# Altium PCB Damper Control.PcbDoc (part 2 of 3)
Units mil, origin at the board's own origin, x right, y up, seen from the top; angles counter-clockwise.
Board outline 4586.61 x 2962.6 mil, 4 copper layers (Top Layer, GND Plane, Power Plane, Bottom Layer), stack 70.356 mil thick; 195 components, 143 nets, 589 pads, 854 vias.
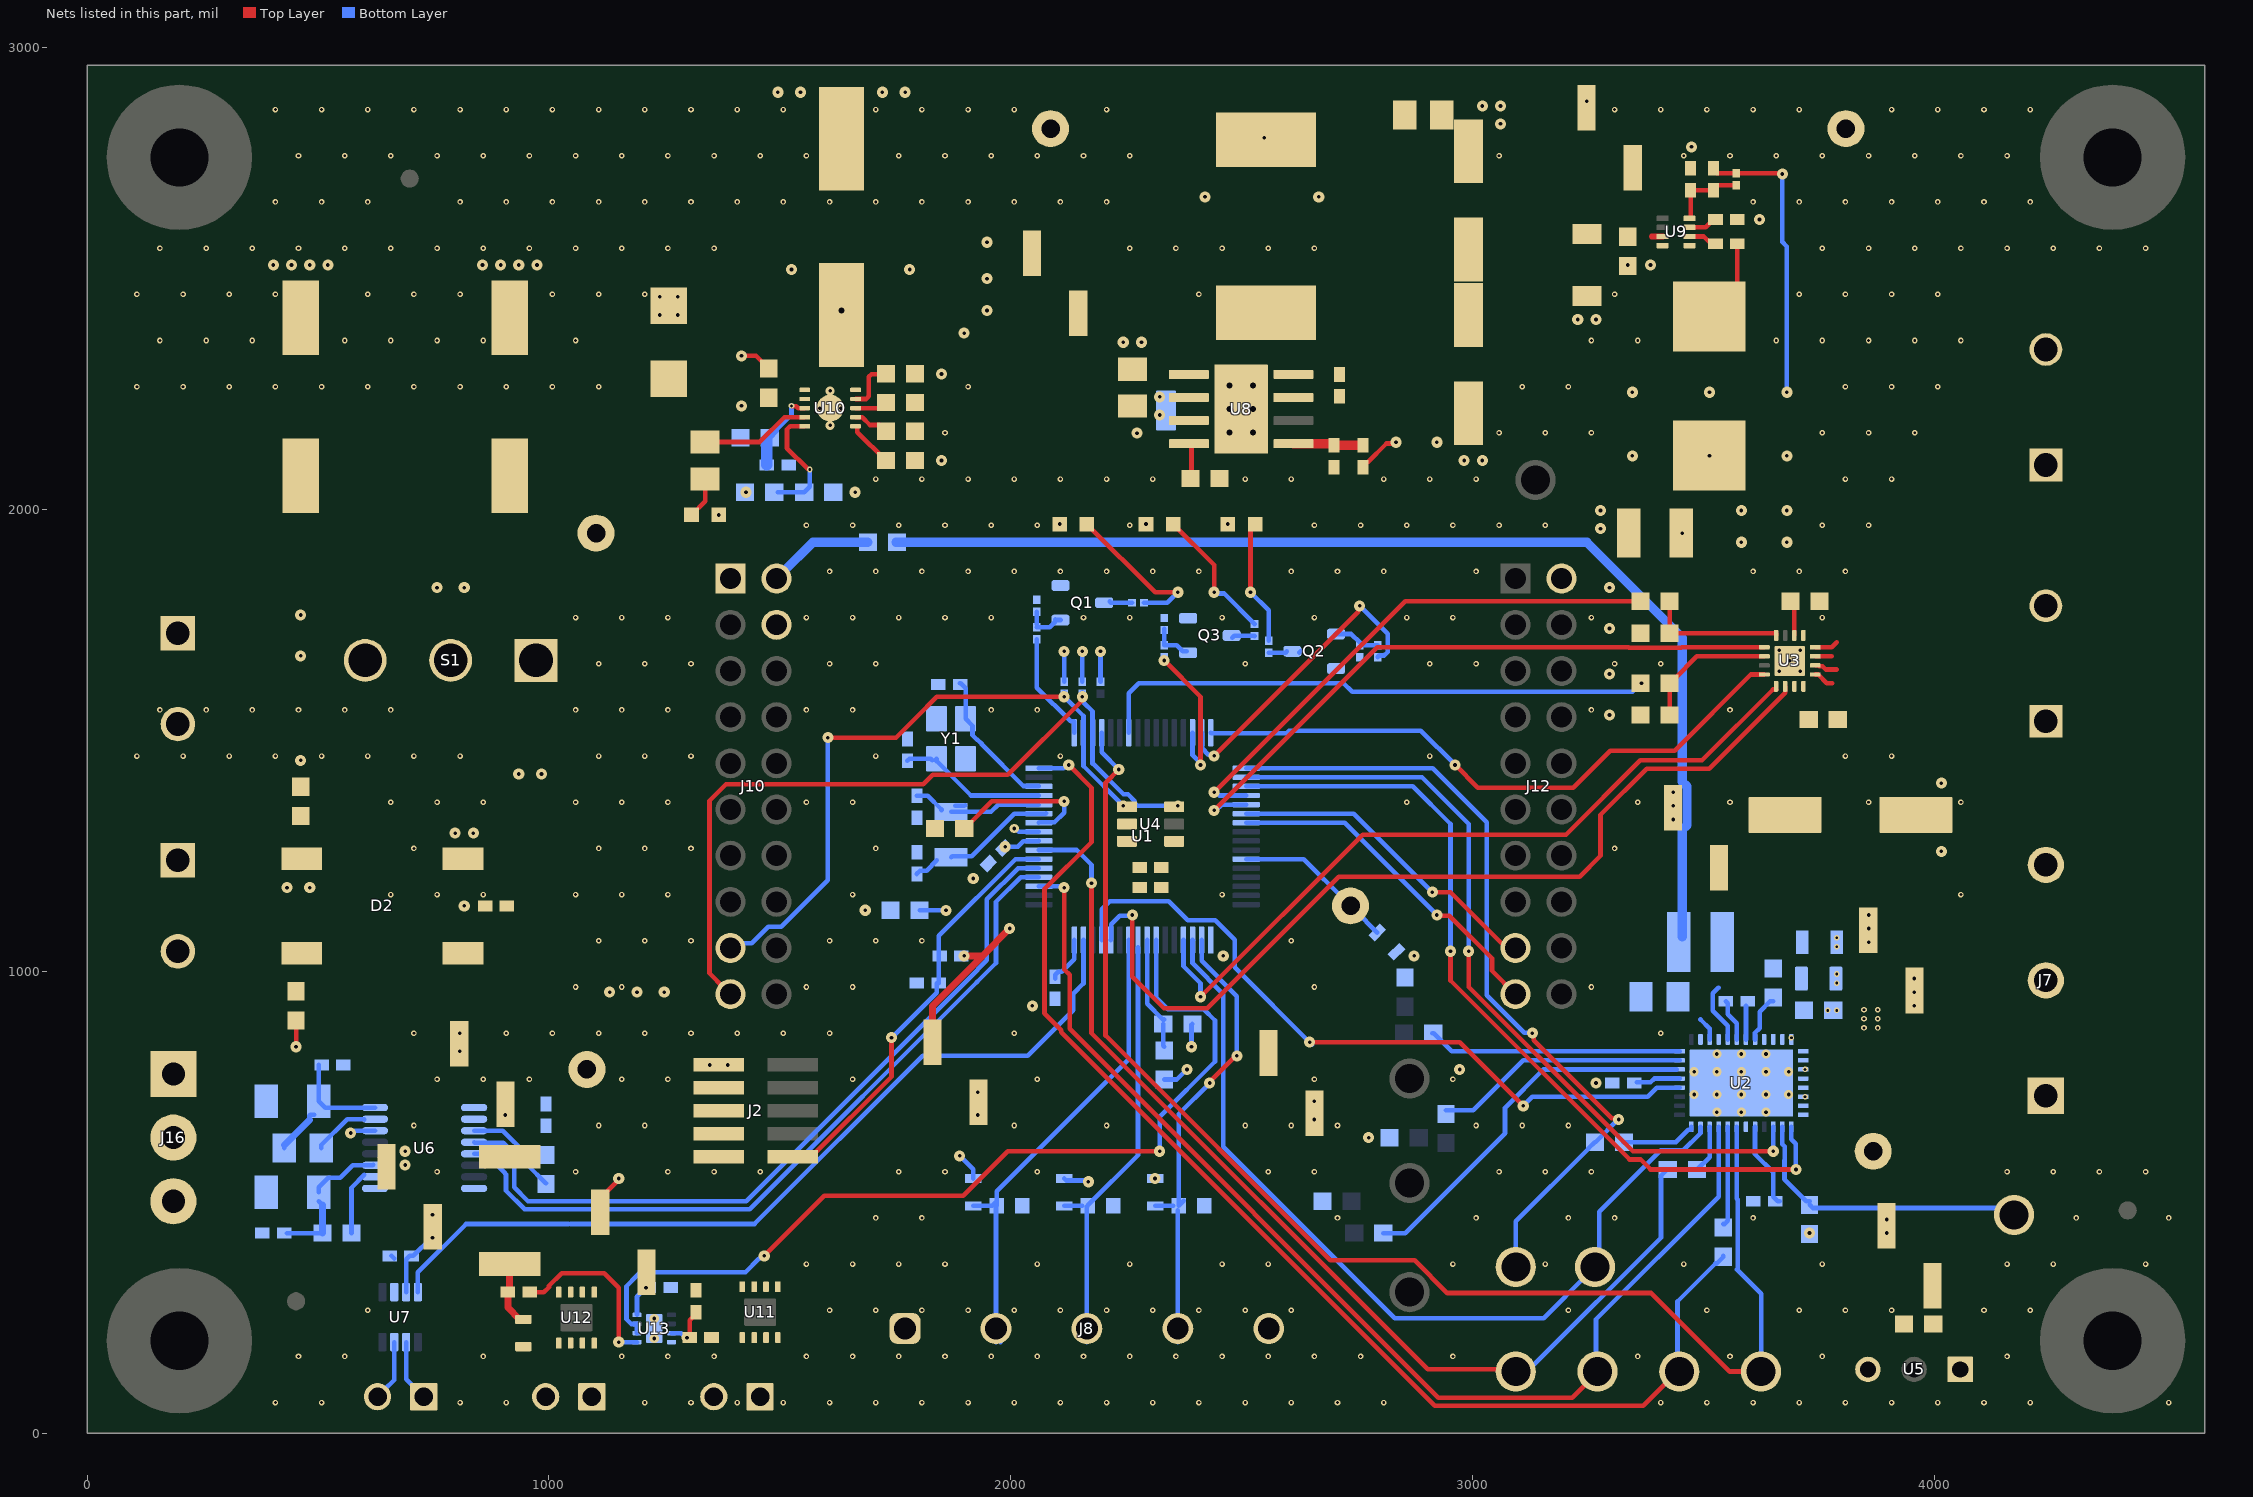
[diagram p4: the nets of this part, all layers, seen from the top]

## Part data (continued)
J7: library part CMP-0055483-1, "Terminal Block, 3x1, 6.35 mm, TH", Manufacturer="Phoenix Contact", Supplier Part Number 1=277-1270-ND
J8: library part CMP-0055532-1, "Terminal Block, 5mm, 5x1, R/A, TH", Color=Green, Current_A=16A, Manufacturer="Phoenix Contact", Supplier Part Number 1=277-2521-ND, Voltage_V=400V
J10 J12: library part CMP-0075442-1, "Connector, Receptacle, 100mil, 10x2, Gold plated, TH", Manufacturer=Samtec
J15 J21 J22: library part CMP-0002337-1, "Header, 100mil, 2x1, Tin, TH", Color=Black, Current_A=3A, Manufacturer="Sullins Connector Solutions", Supplier Part Number 1=S1012E-02-ND, Voltage_V=1.8kV
J16: library part CMP-0074916-1, "Terminal Block, 3.5mm Pitch, 3x1, TH", Color=Grey, Current_A=6A, Manufacturer="On-Shore Technology", Supplier Part Number 1=ED1515-ND, Voltage_V=150V
J18 J19: library part CMP-0055486-1, "TERM BLOCK 2POS 5mm, TH", Manufacturer="Phoenix Contact", Supplier Part Number 1=651-1729018
L1: library part CMP-0059315-2, "Inductor, Drum Core, Ferrite, 47 uH, 0.2 A, 1.5 ohm, SMD", Manufacturer="NIC Components", Value1="1.5 ohm", Value2=0.2A, ValueDisplayed=47uH
L2: library part CMP-0061458-2, "Inductor, Shielded, Ferrite, 68 uH, 4.3 A, 0.074 ohm, SMD", Manufacturer=Coilcraft, Supplier Part Number 1=994-MSS1210-683MEB, Value1="0.074 ohm", Value2=4.3A, ValueDisplayed=68uH
L3: library part CMP-0098677-1, "WE-HCI SMT Flat Wire High Current Inductor, size 1050, 7.8uH, 10.7A, 13.6mOhm", Case/Size Code=1050, DC Resistance=13.6mOhm, Inductance=7.8uH, Manufacturer="Wurth Elektronik", Operating Temperature Max=150°C, Operating Temperature Min=-40°C, Performance Rated Current=10.7A, Saturation Current=9.5A, Self Resonant Frequency=23MHz
Logo1: library part CMP-0074838-1, "Texas Instrument Corporate Signature"
Logo2: library part CMP-0074844-1
Logo3: library part CMP-0074847-1, "FCC_disclaimer"
Logo4: library part CMP-0074769-3, Manufacturer="Texas Instruments"
Q1 Q2 Q3: library part CMP-0000461-2, "Transistor, NPN, 40 V, 0.6 A, SOT-23", Manufacturer="ON Semiconductor", Supplier Part Number 1=MMBT2222ALT1GOSCT-ND, Value1="0.6 A"
R1: library part CMP-0027294-2, "RES, 100, 1%, 0.05 W, 0201", Manufacturer="Yageo America", Power_W=50mW, Supplier Part Number 1=311-100MCT-ND, TempCo="200 ppm/C", Tolerance_%=1%, Value2=0.05W, Value_Code=100R, ValueDisplayed=100
R2 R41 R44: library part CMP-0028069-1, "RES, 100 k, 1%, 0.05 W, 0201", Manufacturer="Yageo America", Power_W=50mW, Supplier Part Number 1=603-RC0201FS-7D100KL, TempCo="200 ppm/C", Tolerance_%=1%, Value2=0.05W, Value_Code=100k
R3 R42 R45: library part CMP-0027131-1, "RES, 4.7 k, 5%, 0.05 W, 0201", Manufacturer="Yageo America", Power_W=50mW, Supplier Part Number 1=311-4.7KNCT-ND, TempCo="200 ppm/C", Tolerance_%=5%, Value2=0.05W, Value_Code=4k70, ValueDisplayed=4.7k
R4: library part CMP-0023630-3, "RES, 100 k, 0.1%, 0.1 W, 0603", Manufacturer="Yageo America", Power_W=100mW, Supplier Part Number 1=603-RT0603BRD07100KL, TempCo="25 ppm/C", Tolerance_%=0.1%, Value2=0.1W, Value_Code=100k
R5: library part CMP-0026935-3, "RES, 47 k, 5%, 0.063 W, AEC-Q200 Grade 0, 0402", Manufacturer=Vishay-Dale, Power_W=63mW, Supplier Part Number 1=541-47KJCT-ND, TempCo="200 ppm/C", Tolerance_%=5%, Value2=0.063W, Value_Code=47k0, ValueDisplayed=47k
R6 R7 R8 R9 R10 R11 R12 R23 R47: library part CMP-0025697-4, "RES, 0, 5%, 0.1 W, AEC-Q200 Grade 0, 0603", Manufacturer=Vishay-Dale, Power_W=100mW, Supplier Part Number 1=541-0.0GCT-ND, TempCo="200 ppm/C", Tolerance_%=5%, Value2=0.1W, Value_Code=0000, ValueDisplayed=0
R13: library part CMP-0025830-4, "RES, 5.1 k, 5%, 0.1 W, AEC-Q200 Grade 0, 0603", Manufacturer=Vishay-Dale, Power_W=100mW, Supplier Part Number 1=541-5.1KGCT-ND, TempCo="200 ppm/C", Tolerance_%=5%, Value2=0.1W, Value_Code=5k10, ValueDisplayed=5.1k
R14 R15 R16: library part CMP-0025729-4, "RES, 1.0 k, 5%, 0.1 W, AEC-Q200 Grade 0, 0603", Manufacturer=Vishay-Dale, Power_W=100mW, Supplier Part Number 1=541-1.0KGCT-ND, TempCo="200 ppm/C", Tolerance_%=5%, Value2=0.1W, Value_Code=1k00, ValueDisplayed=1.0k
R17 R18 R19 R53: library part CMP-0025686-1, "RES, 10.0 k, 0.1%, 0.1 W, AEC-Q200 Grade 1, 0603", Manufacturer=Vishay-Dale, Power_W=100mW, Supplier Part Number 1=TNP10.0KAACT-ND, TempCo="25 ppm/C", Tolerance_%=0.1%, Value2=0.1W, Value_Code=10k0, ValueDisplayed=10.0k
R20 R21 R22: library part CMP-0027242-1, "RES, 4.7 k, 5%, 0.05 W, 0201", Manufacturer="Yageo America", Power_W=50mW, Supplier Part Number 1=603-RC0201JR-7D4K7L, TempCo="200 ppm/C", Tolerance_%=5%, Value2=0.05W, Value_Code=4k70, ValueDisplayed=4.7k
R24: library part CMP-0019016-2, "RES, 562, 0.1%, 0.125 W, 0805", Manufacturer="Susumu Co Ltd", Power_W=125mW, Supplier Part Number 1=RG20P562BCT-ND, TempCo="25 ppm/C", Tolerance_%=0.1%, Value2=0.125W, Value_Code=562R, ValueDisplayed=562
R25: library part CMP-0024912-2, "RES, 200, 0.5%, 0.1 W, 0603", Manufacturer="Yageo America", Power_W=100mW, TempCo="50 ppm/C", Tolerance_%=0.5%, Value2=0.1W, Value_Code=200R, ValueDisplayed=200
R26 R27: library part CMP-0018797-2, "RES, 1.00 k, 0.1%, 0.25 W, 1206", Manufacturer="TE Connectivity", Power_W=250mW, Supplier Part Number 1=A105676-ND, TempCo="15 ppm/C", Tolerance_%=0.1%, Value2=0.25W, Value_Code=1k00, ValueDisplayed=1.00k
R28: library part CMP-0022544-4, "RES, 64.9 k, 1%, 0.1 W, AEC-Q200 Grade 0, 0603", Manufacturer=Vishay-Dale, Power_W=100mW, Supplier Part Number 1=541-64.9KHCT-ND, TempCo="100 ppm/C", Tolerance_%=1%, Value2=0.1W, Value_Code=64k9, ValueDisplayed=64.9k
R29: library part CMP-0025950-3, "RES, 100 k, 1%, 0.063 W, AEC-Q200 Grade 0, 0402", Manufacturer=Vishay-Dale, Power_W=63mW, Supplier Part Number 1=541-100KLCT-ND, TempCo="100 ppm/C", Tolerance_%=1%, Value2=0.063W, Value_Code=100k
R30: library part CMP-0026553-2, "RES, 7.15 k, 1%, 0.063 W, AEC-Q200 Grade 0, 0402", Manufacturer=Vishay-Dale, Power_W=63mW, Supplier Part Number 1=541-7.15KLCT-ND, TempCo="100 ppm/C", Tolerance_%=1%, Value2=0.063W, Value_Code=7k15, ValueDisplayed=7.15k
R31: library part CMP-0022731-2, "RES, 1.00 M, 1%, 0.125 W, 0603", Manufacturer=Vishay/Beyschlag, Power_W=125mW, Supplier Part Number 1=MCT0603-1.00M-CFCT-ND, TempCo="50 ppm/C", Tolerance_%=1%, Value2=0.125W, Value_Code=1M00, ValueDisplayed=1.00M
R32: library part CMP-0026323-2, "RES, 38.3 k, 1%, 0.063 W, AEC-Q200 Grade 0, 0402", Manufacturer=Vishay-Dale, Power_W=63mW, Supplier Part Number 1=541-38.3KLCT-ND, TempCo="100 ppm/C", Tolerance_%=1%, Value2=0.063W, Value_Code=38k3, ValueDisplayed=38.3k
R33: library part CMP-0025698-4, "RES, 100 k, 5%, 0.1 W, AEC-Q200 Grade 0, 0603", Manufacturer=Vishay-Dale, Power_W=100mW, Supplier Part Number 1=541-100KGCT-ND, TempCo="200 ppm/C", Tolerance_%=5%, Value2=0.1W, Value_Code=100k
R34: library part CMP-0022030-4, "RES, 12.1 k, 1%, 0.1 W, AEC-Q200 Grade 0, 0603", Manufacturer=Vishay-Dale, Power_W=100mW, Supplier Part Number 1=541-12.1KHCT-ND, TempCo="100 ppm/C", Tolerance_%=1%, Value2=0.1W, Value_Code=12k1, ValueDisplayed=12.1k
R35: library part CMP-0020887-3, "RES, 13.7 k, 1%, 0.125 W, AEC-Q200 Grade 0, 0805", Manufacturer=Vishay-Dale, Power_W=125mW, Supplier Part Number 1=541-13.7KCCT-ND, TempCo="100 ppm/C", Tolerance_%=1%, Value2=0.125W, Value_Code=13k7, ValueDisplayed=13.7k
R36: library part CMP-0022659-4, "RES, 95.3 k, 1%, 0.1 W, AEC-Q200 Grade 0, 0603", Manufacturer=Vishay-Dale, Power_W=100mW, Supplier Part Number 1=541-95.3KHCT-ND, TempCo="100 ppm/C", Tolerance_%=1%, Value2=0.1W, Value_Code=95k3, ValueDisplayed=95.3k
R37: library part CMP-0025862-4, "RES, 8.2 k, 5%, 0.1 W, AEC-Q200 Grade 0, 0603", Manufacturer=Vishay-Dale, Power_W=100mW, Supplier Part Number 1=541-8.2KGCT-ND, TempCo="200 ppm/C", Tolerance_%=5%, Value2=0.1W, Value_Code=8k20, ValueDisplayed=8.2k
R38: library part CMP-0026285-2, "RES, 30.9 k, 1%, 0.063 W, AEC-Q200 Grade 0, 0402", Manufacturer=Vishay-Dale, Power_W=63mW, Supplier Part Number 1=541-30.9KLCT-ND, TempCo="100 ppm/C", Tolerance_%=1%, Value2=0.063W, Value_Code=30k9, ValueDisplayed=30.9k
R39 R50: library part CMP-0025958-3, "RES, 10.0 k, 1%, 0.063 W, AEC-Q200 Grade 0, 0402", Manufacturer=Vishay-Dale, Power_W=63mW, Supplier Part Number 1=541-10.0KLCT-ND, TempCo="100 ppm/C", Tolerance_%=1%, Value2=0.063W, Value_Code=10k0, ValueDisplayed=10.0k
R40 R43: library part CMP-0027526-1, "RES, 261, 1%, 0.05 W, 0201", Manufacturer="Yageo America", Power_W=50mW, Supplier Part Number 1=YAG2541CT-ND, TempCo="200 ppm/C", Tolerance_%=1%, Value2=0.05W, Value_Code=261R, ValueDisplayed=261
R46: library part CMP-0025885-5, "RES, 0, 5%, 0.1 W, 0603", Manufacturer=Yageo, Power_W=100mW, Supplier Part Number 1=311-0.0GRCT-ND, TempCo="200 ppm/C", Tolerance_%=5%, Value2=0.1W, Value_Code=0000, ValueDisplayed=0
R48: library part CMP-0026025-3, "RES, 158 k, 1%, 0.063 W, AEC-Q200 Grade 0, 0402", Manufacturer=Vishay-Dale, Power_W=63mW, Supplier Part Number 1=541-158KLCT-ND, TempCo="100 ppm/C", Tolerance_%=1%, Value2=0.063W, Value_Code=158k
R49: library part CMP-0026403-2, "RES, 49.9 k, 1%, 0.063 W, AEC-Q200 Grade 0, 0402", Manufacturer=Vishay-Dale, Power_W=63mW, Supplier Part Number 1=541-49.9KLCT-ND, TempCo="100 ppm/C", Tolerance_%=1%, Value2=0.063W, Value_Code=49k9, ValueDisplayed=49.9k
R51: library part CMP-0015444-3, "RES, 120, 1%, 1 W, AEC-Q200 Grade 0, 2512", Manufacturer=Vishay-Dale, Power_W=1W, Supplier Part Number 1=541-120AFCT-ND, TempCo="100 ppm/C", Tolerance_%=1%, Value_Code=120R, ValueDisplayed=120
R52: library part CMP-0037671-1, "12 kOhms ±0.1% 0.1W, 1/10W Chip Resistor 0603 (1608 Metric) Anti-Sulfur, Automotive AEC-Q200, Moisture Resistant Thin Film", Digikey Part Number=541-9817-1-ND, Manufacturer=Vishay, Mouser Part Number=71-TNPW060312K0BYEN, Operating Temperature Range="-55°C to +155°C", Power_W=100mW, TempCo=10ppm/°C, Tolerance_%=0.1%
S1: library part CMP-0002255-1, "Switch, Slide, SPDT, On-Off-On, 1 Pos, 6A, 120 VAC, 28 VDC, TH", CurrentRating_mA=6kA, Manufacturer="C&K Components", Supplier Part Number 1=CKN5051-ND
TP1 TP2 TP3 TP4 TP5 TP6 TP8: library part CMP-0055155-2, "Test Point, Compact, Blue, TH", Color=Blue, Manufacturer="Keystone Electronics", PartNumber=5122, Supplier Part Number 1=36-5122-ND
TP7 TP13 TP14 TP15: library part CMP-0055155-2, "Test Point, Compact, Blue, TH", Color=Blue, Manufacturer="Keystone Electronics", Supplier Part Number 1=36-5122-ND
TP9 TP10 TP16 TP19: library part CMP-0055138-2, "Test Point, Miniature, Black, TH", Color=Black, Manufacturer="Keystone Electronics", PartNumber=5001, Supplier Part Number 1=36-5001-ND
TP11: library part CMP-0055154-1, "Test Point, Miniature, Blue, TH", Color=Blue, Manufacturer=Keystone, Supplier Part Number 1=36-5117-ND
TP20: library part CMP-0055137-2, "Test Point, Miniature, Red, TH", Color=Red, Manufacturer="Keystone Electronics", PartNumber=5000, Supplier Part Number 1=36-5000-ND
U1: library part CMP-0093960-1, "Mixed-Signal Microcontrollers With CAN-FD Interface LQFP64", Frequency_Fixed=80MHz, Manufacturer="Texas Instruments", Max Supply Voltage=3.6V, Min Supply Voltage=1.62V, Operating Temperature Range="-40°C to +125°C"
U2: library part CMP-0096344-1, "Three-Phase Integrated FET Motor Driver", Manufacturer="Texas Instruments", Max Supply Voltage=35V, Min Supply Voltage=4.5V, Nominal Supply Current=1.5-19000uA, Operating Temperature Range="-40°C to +150°C", Switching Frequency=400kHz
U3: library part CMP-0861028-1, "Stepper Drivers With Integrated Current Sense, 1/256 Microstepping, STEP/DIR Interface and smart tune Technology, RTE0016J (WQFN-16)", Alternate Manufacturer="Texas Instruments"
U4: library part CMP-0090454-1, "3-Axis Linear Hall Effect Sensor With I2C Interface", Manufacturer="Texas Instruments", Max Supply Voltage=5.5V, Min Supply Voltage=2.3V, Operating Supply Current=2.8mA, Operating Temperature Range="-40°C to +150°C"
U5: library part CMP-0074653-4, "Precision Analog Output Temperature Sensor, LP0003A (TO-92-3)", Alternate Manufacturer="Texas Instruments", Operating Temperature Range="-40 to 150 C", Rating=Catalog
U6: library part CMP-0013034-2, "ISO1212DBQR, DBQ00016A, DBQ0016A (SSOP-16)", Alternate Manufacturer="Texas Instruments", Alternate PartNumber=ISO1212DBQ
U7: library part CMP-0080984-2, "3.3-V CAN Transceivers with CAN FD (Flexible Data Rate), DCN0008A (SOT-23-8)", Alternate Manufacturer="Texas Instruments", Alternate PartNumber=TCAN334GDCNT
U8: library part CMP-0094072-1, "SIMPLE SWITCHER 4.2-V to 80-V, 2-A Synchronous Buck Converter", Manufacturer="Texas Instruments", Max Supply Voltage=80V, Min Supply Voltage=4.2V, Nominal Supply Current=40uA, Operating Temperature Range="-40°C to +150°C", Output Voltage=1-75V, Switching Frequency=200-1100kHz
U9: library part CMP-0094457-2, "3.8-V to 30-V, 2-A Synchronous Buck Converter in SOT583 Package", Manufacturer="Texas Instruments", Max Supply Voltage=30V, Min Supply Voltage=3.8V, Nominal Supply Current=12uA, Operating Temperature Range="-40°C to +150°C", Output Voltage=0.8-22V, Switching Frequency=310-2100kHz
U10: library part CMP-0093898-1, Manufacturer="Texas Instruments", Operating Temperature Range=to
U11 U12: library part CMP-0083941-3, "14 V Bidirectional Flat-Clamp Surge Protection Device, DRB0008A (VSON-8)", Alternate Manufacturer="Texas Instruments", Alternate PartNumber=TVS1401DRBR, Operating Temperature Range="-40 to 125 C"
U13: library part CMP-0860798-1, "2-Channel, 1MHz, RRIO, 1.8V to 5.5V Operational Amplifier for Cost-Optimized Systems, DSG0008A (WSON-8)", Alternate Manufacturer="Texas Instruments", Alternate PartNumber=TLV9002IDSGT, Operating Temperature Range="-40 to 125 C", Rating=Catalog
Y1: library part CMP-0098168-2, "Crystal 40MHz ±10ppm (Tol) ±20ppm (Stability) 12pF FUND 40Ohm 4-Pin Mini-CSMD T/R", Frequency Stability=20ppm, Frequency Tolerance=10ppm, Frequency_Fixed=40MHz, Load Capacitance=12pF, Manufacturer="Seiko Epson", Operating Temperature Range="-40°C to +105°C"
Y2: library part CMP-0004693-3, "Crystal, 32.768 KHz, 12.5 pF, SMD", Frequency_Fixed=32.768kHz, Manufacturer=Epson
ZZ1: library part CMP-0003616-3
ZZ2: library part CMP-0077236-1
ZZ3: library part CMP-0077237-1
ZZ4: library part CMP-0077238-1

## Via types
v1: diameter 12, hole 6, Top Layer to Bottom Layer, tented both sides, 463 vias
v2: diameter 24, hole 8, Top Layer to Bottom Layer, tented both sides, 202 vias
v3: diameter 12, hole 6, Top Layer to Bottom Layer, 145 vias
v4: diameter 19.68, hole 7.87, Top Layer to Bottom Layer, 19 vias
v5: diameter 19.68, hole 7.87, Top Layer to Bottom Layer, tented both sides, 16 vias
v6: diameter 24.8, hole 12.99, Top Layer to Bottom Layer, 7 vias
v7: diameter 20, hole 8, Top Layer to Bottom Layer, tented both sides, 1 vias
v8: diameter 24, hole 8, Top Layer to Bottom Layer, 1 vias

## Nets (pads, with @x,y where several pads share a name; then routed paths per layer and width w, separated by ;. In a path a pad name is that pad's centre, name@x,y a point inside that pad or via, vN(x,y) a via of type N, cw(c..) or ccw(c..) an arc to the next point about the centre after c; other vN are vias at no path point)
0_10VDC: J15.1 R48.2 U11.1 U11.2 U11.3 U11.4
3V3: C49.1 C51.1 D1.1 D5.1 D6.1 J1.1 J2.1 J8.5 J9.1 J10.1 J11.1 J13.1 J14.1 J23.1 L3.2 R13.1 R17.2 R18.2 R19.2 R20.2 R21.2 R22.2 R38.2 R46.1 | length 1094.2
  Top Layer w10: J23.1@1111.42,478.54 1111.42,508.27 1151.57,548.43 v2(1151.57,551.18) ; R38.2@3523.15,2739.11 R38.2@3522.68,2738.64 3522.68,2734.82 3529.49,2728.01 C49.1@3571.21,2728.01 ; C49.1@3571.9,2728.01 v2@3673.02,2728.01
  Bottom Layer w10: v2(1889.76,600.39) 1919.29,570.87 R19.2@1919.29,551.18 ; R18.2@2116.14,551.18 2120.41,546.92 2161.94,546.92 2165.35,543.5 v2@2165.35,541.34 ; R20.2@2116.14,1627.17 v2(2116.14,1692.91) ; R21.2@2155.51,1627.17 v2(2155.51,1692.91) ; R22.2@2194.88,1627.17 v2(2194.88,1692.91) ; R46.1@2332.68,765.75 2360.24,765.75 v2(2381.89,787.4) ; v2(3671.26,2726.38) 3671.26,2579.43 3681.1,2569.59 v2(3681.1,2253.94)
  other v2: 3730.32,433.07 3897.64,433.07 3897.64,462.6 2168.41,544.24 2312.99,551.18 688.98,580.71 688.98,610.24 2657.48,679.13 1929.13,688.98 2657.48,718.5 1929.13,738.19 1348.43,797.24 1387.8,797.24 807.09,826.77 807.09,866.14 3582.68,1929.13 3681.1,1929.13 3454.72,1948.82 2106.3,1968.5 2293.31,1968.5 2470.47,1968.5 3582.68,1998.03 3681.1,1998.03 3346.46,2116.14 3513.78,2116.14 3681.1,2116.14 3513.78,2253.94
  other v8: 3346.46,2253.94
4_20mA: J22.1 R52.1 U12.1 U12.2 U12.3 U12.4
5V: C19.2 L1.2 R47.2 U2.3 | length 2495.9
  Bottom Layer w10: 3494.09,895.67 3513.78,875.98 U2.3@3513.78,852.36
  Bottom Layer w20: R47.2@1751.97,1929.13 R47.2@1753.94,1929.13 3248.03,1929.13 3454.72,1722.44 3454.72,1410.36 3464.91,1400.17 3464.91,1316.37 3454.72,1306.18 L1.2@3454.72,1074.8
15VDC: C39.1 C40.1 C41.1 J3.1 J4.1 J20.1 L2.2 R29.2 | length 96.4
  Top Layer w10: R29.2@2762.87,2091.72 2762.87,2095.66 2769.68,2102.47 2773.62,2102.47 2814.14,2142.99 2831.97,2142.99 v2(2834.65,2145.67)
  other v2: 3956.69,925.2 3956.69,954.72 3956.69,984.25 3435.04,1328.74 3435.04,1358.27 3435.04,1387.8 2923.23,2145.67 2421.26,2677.17 2667.32,2677.17 2549.21,2805.12 3248.03,2883.86
24VDC_IN: J19.1 S1.3
  other v2: 462.6,1683.07 462.6,1771.65
AOUT1: J6.1 U3.1 | length 44.8
  Top Layer w10: U3.1@3742.51,1642.71 3749.05,1642.71 3767.74,1624.02 3779.53,1624.02
AOUT2: J6.2 U3.2 | length 50.5
  Top Layer w10: U3.2@3742.51,1662.4 3749.05,1662.4 3750.86,1660.58 3758.22,1660.58 3765.26,1653.54 3789.37,1653.54
AVDD: C15.1 U2.25 | length 185.7
  Bottom Layer w10: U2.25@3612.2,663.39 3612.2,603.88 3651.57,564.51 3651.57,511.81 3661.42,501.97 C15.1@3665.35,501.97
BOUT1: J5.2 U3.4 | length 51.3
  Top Layer w10: U3.4@3742.51,1701.77 3778.54,1701.77 3789.37,1712.6
BOUT2: J5.1 U3.3 | length 36
  Top Layer w10: U3.3@3742.51,1682.08 3778.54,1682.08
C_Ctrl: U1.23 U13.6 U13.7 | length 2004.4
  Top Layer w10: v2(1466.54,383.86) 1596.3,513.62 1897.17,513.62 1993.78,610.24 v2@2327.98,610.24
  Bottom Layer w10: U13.6@1190.94,216.54 U13.7@1190.94,236.22 1178.81,236.22 1168.23,246.8 1168.23,317.84 1190.94,340.56 1198.5,348.11 1426.03,348.11 1455.07,377.14 1456.03,377.14 1462.75,383.86 v2(1466.54,383.86) ; U1.23@2315.36,1067.71 2315.36,942.51 2340.47,917.4 2418.72,917.4 2442.76,893.36 2442.76,804.7 2322.83,684.78 v2(2322.83,610.24)
CANH: J21.2 U7.7 | length 117.4
  Bottom Layer w10: J21.2@639.76,98.43 643.43,94.76 645.16,94.76 665.35,114.96 U7.7@665.35,196.85
CANL: J21.1 U7.6 | length 159
  Bottom Layer w10: U7.6@690.94,196.85 690.94,116.93 709.45,98.43 J21.1@728.35,98.43 ; J21.1@729.13,68.9 J21.1@753.19,92.95
DECAY_TOFF: U1.5 U3.9 | length 1413.1
  Top Layer w10: v2(2440.95,1348.43) 2794.29,1701.77 3338.1,1701.77 3339.16,1700.71 3452.18,1700.71 3453.24,1701.77 U3.9@3632.28,1701.77
  Bottom Layer w10: v2(2440.95,1348.43) 2444.73,1348.43 2457.33,1361.02 U1.5@2510.25,1361.02
DIR: U1.64 U3.12 | length 1353.9
  Top Layer w10: v2(2962.6,1446.85) 3011.81,1397.64 3218.5,1397.64 3298.74,1477.87 3438.06,1477.87 3602.9,1642.71 U3.12@3632.28,1642.71
  Bottom Layer w10: U1.64@2433.47,1516.53 2434.26,1515.75 2597.7,1515.75 2602.89,1520.94 2888.51,1520.94 v2(2962.6,1446.85)
DRV_OFF: U1.3 U2.21 | length 1829.2
  Top Layer w10: v2(2952.76,1043.31) 2952.76,980.06 3340.45,592.36 3364.33,592.36 3385.83,570.87 v2(3700.79,570.87)
  Bottom Layer w10: U1.3@2510.25,1400.39 2871.26,1400.39 2952.76,1318.9 v2(2952.76,1043.31) ; U2.21@3690.94,663.39 3690.94,636.44 3700.79,626.6 v2(3700.79,570.87)
EFuse_IN: C37.1 C38.1 C42.1 D3.1 D4.1 R31.2 R33.1 S1.2 TP20.1 U10.1 U10.2
  other v2: 757.87,1830.71 816.93,1830.71 1368.11,1988.19 1427.17,2037.4 1417.32,2224.41
EFuse_OUT: C50.1 J17.1 U10.10
  other v2: 1899.61,2381.89 1948.82,2431.1 1948.82,2500 1525.59,2519.69 1781.5,2519.69 1948.82,2578.74
  other v6: 1633.86,2431.1
EN_FAULT: U1.20 U3.13 | length 1660
  Top Layer w10: v2(2411.42,944.88) 2762.28,1295.75 3202.8,1295.75 3363.75,1456.69 3497.44,1456.69 3651.06,1610.31 U3.13@3657.59,1610.31
  Bottom Layer w10: U1.20@2374.42,1067.71 2374.42,1011.41 2411.42,974.41 v2(2411.42,944.88)
F_GND: C52.2 C55.2 J16.3 U6.9 U6.14 | length 54.9
  Bottom Layer w10: v2(570.87,649.61) 574.65,649.61 579.83,654.79 U6.14@623.65,654.79
F_IN1: J16.1 R26.2
F_IN2: J16.2 R27.2
GND: C1.2 C2.2 C3.2 C4.2 C5.2 C6.2 C7.2 C8.2 C9.2 C10.1 C11.2 C13.2 C15.2 C18.2 C19.1 C20.2 C21.2 C22.2 C23.2 C24.2 C25.2 C26.2 C27.2 C28.2 C29.2 C30.2 C31.1 C32.2 C33.2 C34.2 C35.2 C37.2 C38.2 C39.2 C40.2 C41.2 C42.2 C43.2 C44.2 C45.2 C47.1 C48.1 C50.2 C51.2 C54.1 D2.2 D3.2 J2.3 J2.5 J2.7 J2.9 J8.1 J10.4 J12.2 J15.2 J19.2 J22.2 Q1.2 Q2.2 Q3.2 R2.1 R4.2 R7.1 R12.1 R28.1 R30.1 R32.1 R34.1 R36.2 R37.2 R39.1 R41.1 R44.1 R49.1 R51.1 R53.2 TP9.1 TP16.1 TP19.1 U1.17 U1.41 U2.2 U2.4 U2.26 U2.41 U3.5 U3.16 U3.17 U4.2 U4.3 U5.3 U6.1 U6.8 U7.2 U8.1 U8.9 U9.4 U10.11 U11.5 U11.6 U11.7 U11.8 U12.5 U12.6 U12.7 U12.8 U13.4 U13.9@1228.35,226.38 Y1.2 Y1.4 | length 243
  Top Layer w10: v2(452.76,836.61) C33.2@452.76,893.7 ; v2(1417.32,2332.68) 1448.82,2332.68 1461.69,2319.8 1462.68,2319.8 1476.38,2306.1 C42.2@1476.38,2305.12
  Bottom Layer w10: C30.2@659.45,383.86 C30.2@665.35,377.95 ; v7(2007.87,1309.06) 2010.58,1309.06 2017.67,1301.97 U1.41@2061.43,1301.97 ; v2(2391.73,836.61) 2391.73,883.86 C9.2@2393.7,885.83
  other v1: 408,66 508,66 808,66 908,66 1208,66 1308,66 1408,66 1508,66 1608,66 1708,66 1808,66 1908,66 2008,66 2108,66 2208,66 2308,66 2408,66 2508,66 2608,66 2708,66 2808,66 3408,66 3508,66 3608,66 3708,66 3808,66 3908,66 4008,66 4108,66 4208,66 4508,66 458,166 558,166 858,166 1158,166 1258,166 1358,166 1558,166 1658,166 1758,166 1858,166 1958,166 2058,166 2158,166 2258,166 2358,166 2458,166 2558,166 2658,166 2758,166 2958,166 3358,166 3558,166 3758,166 4158,166 608,266 1608,266 1708,266 1808,266 1908,266 2008,266 2108,266 2208,266 2308,266 2408,266 2508,266 2608,266 3208,266 3508,266 3708,266 3808,266 3908,266 4108,266 4208,266 1558,366 1658,366 1758,366 1858,366 2058,366 2258,366 2458,366 2558,366 2958,366 3158,366 3458,366 3758,366 4158,366 4258,366 4458,366 1708,466 1808,466 2708,466 3008,466 3208,466 3308,466 3608,466 4308,466 4508,466 758,566 1058,566 1258,566 1358,566 1458,566 1758,566 1858,566 2058,566 2558,566 2658,566 3058,566 3158,566 3258,566 4158,566 4258,566 4358,566 4458,566 708,666 1108,666 1208,666 2008,666 2208,666 2508,666 2608,666 2708,666 3008,666 3108,666 3208,666 758,766 858,766 958,766 1158,766 1258,766 1658,766 2058,766 2658,766 2958,766 708,866 908,866 1008,866 1108,866 1208,866 1308,866 1408,866 1508,866 1608,866 2008,866 3408,866 1058,966 1158,966 1558,966 1658,966 2658,966 3258,966 1108,1066 1208,1066 1308,1066 1608,1066 1708,1066 1808,1066 2608,1066 658,1166 758,1166 858,1166 1058,1166 1158,1166 1258,1166 1658,1166 2458,1166 4058,1166 708,1266 1108,1266 1208,1266 1308,1266 1708,1266 3308,1266 658,1366 758,1366 858,1366 1058,1366 1158,1366 1258,1366 1558,1366 1658,1366 2858,1366 3358,1366 3558,1366 3858,1366 4058,1366 108,1466 208,1466 308,1466 408,1466 508,1466 608,1466 708,1466 808,1466 1108,1466 1208,1466 1308,1466 1708,1466 2108,1466 2908,1466 3808,1466 3908,1466 158,1566 258,1566 358,1566 458,1566 558,1566 658,1566 1058,1566 1158,1566 1258,1566 1558,1566 1658,1566 1958,1566 2058,1566 3258,1566 3558,1566 1108,1666 1208,1666 1308,1666 1608,1666 1708,1666 2508,1666 2908,1666 3008,1666 3308,1666 3408,1666 1058,1766 1158,1766 1258,1766 1558,1766 1658,1766 1758,1766 1858,1766 1958,1766 2158,1766 2258,1766 2458,1766 2658,1766 2858,1766 2958,1766 3258,1766 3758,1766 1608,1866 1708,1866 1808,1866 1908,1866 2008,1866 2108,1866 2208,1866 2308,1866 2408,1866 2608,1866 2708,1866 2808,1866 3008,1866 3608,1866 3708,1866 3808,1866 1558,1966 1658,1966 1758,1966 1858,1966 1958,1966 2058,1966 2258,1966 2658,1966 2758,1966 2858,1966 2958,1966 3058,1966 3158,1966 3758,1966 3858,1966 1708,2066 1808,2066 1908,2066 2008,2066 2108,2066 2208,2066 2308,2066 2508,2066 2608,2066 2808,2066 2908,2066 3008,2066 3808,2066 3908,2066 1858,2166 3058,2166 3158,2166 3258,2166 3758,2166 3858,2166 3958,2166 108,2266 208,2266 308,2266 408,2266 508,2266 608,2266 708,2266 808,2266 908,2266 1008,2266 1108,2266 1908,2266 3108,2266 3208,2266 3808,2266 3908,2266 4008,2266 158,2366 258,2366 358,2366 558,2366 658,2366 758,2366 858,2366 1058,2366 3258,2366 3358,2366 3658,2366 3758,2366 3858,2366 3958,2366 4058,2366 108,2466 208,2466 308,2466 408,2466 608,2466 708,2466 808,2466 1008,2466 1108,2466 1208,2466 2408,2466 3308,2466 3708,2466 3808,2466 3908,2466 4008,2466 158,2566 258,2566 358,2566 458,2566 558,2566 658,2566 758,2566 858,2566 958,2566 1058,2566 1158,2566 1258,2566 1358,2566 2258,2566 2358,2566 2458,2566 2558,2566 2658,2566 3758,2566 3858,2566 3958,2566 4058,2566 4158,2566 4258,2566 4358,2566 4458,2566 408,2666 508,2666 608,2666 808,2666 908,2666 1008,2666 1108,2666 1208,2666 1308,2666 1408,2666 1508,2666 1608,2666 1708,2666 1808,2666 1908,2666 2008,2666 2108,2666 2208,2666 3608,2666 3708,2666 3808,2666 3908,2666 4008,2666 4108,2666 4208,2666 458,2766 558,2766 658,2766 758,2766 858,2766 958,2766 1058,2766 1158,2766 1258,2766 1358,2766 1458,2766 1558,2766 1758,2766 1858,2766 1958,2766 2058,2766 2158,2766 2258,2766 3058,2766 3458,2766 3558,2766 3658,2766 3758,2766 3858,2766 3958,2766 4058,2766 4158,2766 408,2866 508,2866 608,2866 708,2866 808,2866 908,2866 1008,2866 1108,2866 1208,2866 1308,2866 1408,2866 1508,2866 1708,2866 1808,2866 1908,2866 2008,2866 2208,2866 3308,2866 3408,2866 3508,2866 3608,2866 3708,2866 3908,2866 4008,2866 4108,2866 4208,2866
  other v2: 2775.59,639.76 3267.72,757.87 2972.44,787.4 2047.24,925.2 1131.89,954.72 1190.94,954.72 1250,954.72 2460.63,1033.46 2874.02,1033.46 1685.3,1132.18 816.93,1141.73 1919.29,1200.79 4015.75,1259.84 797.24,1299.21 836.61,1299.21 4015.75,1407.48 462.6,1456.69 3297.24,1555.12 3297.24,1643.7 3297.24,1742.13 3297.24,1830.71 3277.56,1958.66 3277.56,1998.03 1663.39,2037.4 1850.39,2106.3 2982.28,2106.3 3021.65,2106.3 1850.39,2293.31 2244.09,2362.2 2283.46,2362.2 3228.35,2411.42 3267.72,2411.42 1240.16,2421.26 1279.53,2421.26 1240.16,2460.63 1279.53,2460.63 403.54,2529.53 442.91,2529.53 482.28,2529.53 521.65,2529.53 856.3,2529.53 895.67,2529.53 935.04,2529.53 974.41,2529.53 3336.61,2529.53 3385.83,2529.53 3622.05,2627.95 3474.41,2785.43 3060.96,2835.06 3021.65,2874.02 3061.02,2874.02 1496.06,2903.54 1545.28,2903.54 1722.44,2903.54 1771.65,2903.54
  other v3: 1058,966 1158,966 1108,1066 1208,1066 1308,1066 658,1166 758,1166 858,1166 1058,1166 1158,1166 1258,1166 708,1266 1108,1266 1208,1266 1308,1266 658,1366 758,1366 858,1366 1058,1366 1158,1366 1258,1366 108,1466 208,1466 308,1466 408,1466 508,1466 608,1466 708,1466 808,1466 1108,1466 1208,1466 1308,1466 158,1566 258,1566 358,1566 458,1566 558,1566 658,1566 1058,1566 1158,1566 1258,1566 1108,1666 1208,1666 1308,1666 1058,1766 1158,1766 1258,1766 108,2266 208,2266 308,2266 408,2266 508,2266 608,2266 708,2266 808,2266 908,2266 1008,2266 1108,2266 158,2366 258,2366 358,2366 558,2366 658,2366 758,2366 858,2366 1058,2366 108,2466 208,2466 308,2466 408,2466 608,2466 708,2466 808,2466 1008,2466 1108,2466 1208,2466 158,2566 258,2566 358,2566 458,2566 558,2566 658,2566 758,2566 858,2566 958,2566 1058,2566 1158,2566 1258,2566 1358,2566 2258,2566 408,2666 508,2666 608,2666 808,2666 908,2666 1008,2666 1108,2666 1208,2666 1308,2666 1408,2666 1508,2666 1608,2666 1708,2666 1808,2666 1908,2666 2008,2666 2108,2666 2208,2666 458,2766 558,2766 658,2766 758,2766 858,2766 958,2766 1058,2766 1158,2766 1258,2766 1358,2766 1458,2766 1558,2766 1758,2766 1858,2766 1958,2766 2058,2766 2158,2766 2258,2766 408,2866 508,2866 608,2866 708,2866 808,2866 908,2866 1008,2866 1108,2866 1208,2866 1308,2866 1408,2866 1508,2866 1708,2866 1808,2866 1908,2866 2008,2866 2208,2866
  other v4: 1228.35,204.72 1228.35,248.03 3664.56,1649.4 3710.23,1649.4 3687.39,1672.24 3664.56,1695.07 3710.23,1695.07 1609.33,2182.21 1586.7,2219.62 1631.97,2219.62 1609.33,2257.02
  other v5: 3529.53,694.88 3582.68,694.88 3635.83,694.88 3480.31,733.27 3529.53,733.27 3582.68,733.27 3635.83,733.27 3685.04,733.27 3480.31,782.48 3529.53,782.48 3582.68,782.48 3635.83,782.48 3685.04,782.48 3529.53,820.87 3582.68,820.87 3635.83,820.87
  other v6: 2473.79,2166.34 2524.97,2166.34 2473.79,2217.52 2524.97,2217.52 2473.79,2268.7 2524.97,2268.7
GPIO1: J12.17 U1.6 | length 681.2
  Top Layer w10: v2@2919.07,1171.26 2952.76,1171.26 3063.11,1060.91 3088.47,1060.91 J12.17@3090.55,1062.99
  Bottom Layer w10: U1.6@2510.25,1341.34 2743.31,1341.34 v2@2906.01,1178.63
  other v2: 2913.39,1171.26
GPIO2: J12.19 U1.7 | length 752.6
  Top Layer w10: v2(2923.23,1122.05) 2924.89,1120.38 2950.23,1120.38 3042.61,1028 3042.61,1001.09 J12.19@3093.31,950.39
  Bottom Layer w10: U1.7@2510.25,1321.65 2723.62,1321.65 v2(2923.23,1122.05)
HALLA: C23.1 J8.4 R17.1 U1.18 | length 1001
  Top Layer w10: v2(2431.1,757.87) 2431.1,760.65 2487.39,816.93 v2(2490.16,816.93)
  Bottom Layer w10: R17.1@2312.99,492.13 C23.1@2352.36,492.13 ; J8.4@2362.2,196.85 C23.1@2362.2,482.28 ; C23.1@2374.92,502.87 C23.1@2364.17,492.13 2364.17,690.94 v2(2431.1,757.87) ; U1.18@2413.79,1067.71 2413.79,1022.59 2490.16,946.22 v2(2490.16,816.93)
HALLB: C24.1 J8.3 R18.1 U1.25 | length 939.6
  Bottom Layer w10: R18.1@2116.14,492.13 C24.1@2155.51,492.13 ; J8.3@2165.35,196.85 J8.3@2165.35,226.38 2165.35,490.16 C24.1@2167.32,492.13 ; C24.1@2167.32,493.11 2275.99,601.78 U1.25@2275.99,1052.24
HALLC: C25.1 J8.2 R19.1 U1.26 | length 1052
  Bottom Layer w10: R19.1@1919.29,492.13 1959.72,492.13 C25.1@1968.5,500.91 ; J8.2@1968.5,196.85 C25.1@1968.5,492.13 ; C25.1@1970.47,492.13 1970.47,523.62 2027.56,580.71 2256.31,809.46 U1.26@2256.31,1067.71 ; J8.2@1978.35,196.85 J8.2@1978.35,206.69
HFXIN: C6.1 U1.45 Y1.3 | length 314.9
  Bottom Layer w10: C6.1@1776.64,1455.81 1781.09,1460.26 1827.14,1460.26 Y1.3@1830.71,1456.69 ; Y1.3@1839.75,1460.26 1839.75,1455.34 1914.38,1380.71 U1.45@2061.43,1380.71
HFXOUT: C1.1 U1.46 Y1.1 | length 315.8
  Bottom Layer w10: C1.1@1889.76,1624.02 1891.72,1624.02 1902.74,1612.99 Y1.1@1902.74,1546.88 1917.54,1532.07 1917.54,1511.46 1927.3,1501.71 1928.5,1501.71 1938.25,1491.96 1938.25,1490.75 2027.71,1401.3 2060.52,1401.3 U1.46@2061.43,1400.39
I2C1_SCL: J10.17 R20.1 U1.50 U4.1 | length 1439.7
  Top Layer w10: J10.17@1393.31,1053.15 J10.17@1407.48,1053.15 ; v2(1604.33,1505.91) 1751.97,1505.91 1796.26,1550.2 1840.55,1594.49 ; 1841.57,1594.49 v2(2116.14,1594.49) ; U4.1@2242.13,1356.3 v2(2244.09,1358.27)
  Bottom Layer w10: J10.17@1397.64,1053.15 1405.4,1060.91 1439.68,1060.91 1475.03,1096.26 1503.31,1096.26 1604.33,1197.28 v2(1604.33,1505.91) ; v2(2116.14,1594.49) 2157.88,1552.75 2157.88,1444.48 v2(2244.09,1358.27) ; R20.1@2116.14,1604.33 R20.1@2116.14,1601.18 2116.14,1600.39 2119.41,1597.13 R20.1@2121.82,1597.13
I2C1_SDA: J10.19 R21.1 U1.51 U4.6 | length 1745.7
  Top Layer w10: J10.19@1377.95,964.57 1377.95,965.75 1347.95,995.75 1347.95,1369.18 1383.81,1405.04 1811.09,1405.04 1831.41,1425.35 1994.05,1425.35 2152.83,1584.14 2152.83,1591.81 v2(2155.51,1594.49) ; J10.19@1378.54,965.16 J10.19@1393.31,950.39 ; U4.6@2342.52,1358.27 v2(2362.2,1358.27)
  Bottom Layer w10: v2(2155.51,1594.49) 2158.19,1591.81 2158.19,1581.97 2177.57,1562.59 U1.51@2177.57,1516.53 2177.57,1450.07 2244.5,1383.14 2254.4,1383.14 2268.97,1368.57 2268.97,1364.13 2274.83,1358.27 v2(2362.2,1358.27) ; R21.1@2155.51,1600.39 R21.1@2155.51,1601.18 R21.1@2155.51,1604.33
INHA: TP1.1 U1.52 U2.27 | length 2961.2
  Top Layer w10: v2(2234.25,1437.01) 2205.71,1408.47 2205.71,860.9 2692.6,374.02 2875,374.02 2945.82,303.19 3387.75,303.19 3557.75,133.19 3617.44,133.19 TP1.1@3622.05,137.8
  Bottom Layer w10: U1.52@2197.25,1516.53 2197.25,1474.01 v2(2234.25,1437.01) ; 3572.83,354.33 3625.31,301.85 TP1.1@3625.31,133.19 3622.05,136.46 TP1.1@3622.05,137.8 ; U2.27@3572.83,663.39 3572.83,507.75 3574.88,505.7 3574.88,354.33
INHB: TP5.1 U1.35 U2.29 | length 2491.7
  Top Layer w10: v2(2116.14,1181.1) 2116.14,1003.94 2127.8,992.28 2127.8,875.38 2926.36,76.82 3216.58,76.82 3248.03,108.27 TP5.1@3267.72,108.27
  Bottom Layer w10: U1.35@2061.43,1183.86 v2@2113.39,1183.86 ; TP5.1@3267.72,127.95 3267.72,246.06 3533.46,511.81 U2.29@3533.46,663.39
INHC: TP4.1 U1.19 U2.31 | length 1898.7
  Bottom Layer w10: U1.19@2395.01,1066.81 U1.19@2394.1,1067.71 2394.1,1017 2460.63,950.47 2460.63,620.08 2831.96,248.74 3154.53,248.74 3250.28,344.49 TP4.1@3277.56,344.49 ; TP4.1@3267.72,374.02 3275.2,381.5 3275.2,479.43 3407.82,612.05 3456.86,612.05 3494.02,649.21 3494.02,663.31 U2.31@3494.09,663.39
INLA: R9.1 TP3.1 U1.48 | length 2689.8
  Top Layer w10: v2(2125.98,1446.85) 2175.2,1397.64 2175.2,1279.53 2073.39,1177.72 2073.39,908.89 2109.92,872.36 2109.92,867.97 2918.95,58.94 3370.03,58.94 3419.13,108.04 3419.13,114.34 TP3.1@3415.35,118.11
  Bottom Layer w10: U1.48@2061.43,1439.76 2115.55,1439.76 2122.64,1446.85 v2(2125.98,1446.85) ; TP3.1@3444.88,137.8 3444.28,138.4 3444.28,284.83 3526.65,367.2 3529.61,367.2 3543.6,381.2 R9.1@3543.6,384.15
INLB: R10.1 TP2.1 U1.39 | length 2318
  Top Layer w10: v2(2175.2,1190.94) 2175.2,866.14 2903.54,137.8 TP2.1@3087.45,137.8 ; TP2.1@3086.82,127.95 TP2.1@3090.55,127.95
  Bottom Layer w10: U1.39@2061.43,1262.6 2142.92,1262.6 2175.2,1230.32 v2(2175.2,1190.94) v2@2175.2,1189.04 ; TP2.1@3080.71,127.95 TP2.1@3101.29,127.95 ; TP2.1@3090.55,147.64 3090.84,147.92 3133.44,147.92 3408.54,423.03 3408.54,557.17 3422.24,570.87 R10.1@3423.23,570.87
INLC: R11.1 TP6.1 U1.1 | length 1763
  Top Layer w10: v2(3129.92,866.14) 3132.6,863.46 3132.6,850.77 3301.49,681.88 3301.56,681.81 3314.25,681.81 v2(3316.93,679.13)
  Bottom Layer w10: U1.1@2510.25,1439.76 2914.52,1439.76 3031.5,1322.79 3031.5,948.06 3112.58,866.98 3129.08,866.98 v2(3129.92,866.14) ; TP6.1@3090.55,363.18 TP6.1@3094.17,359.57 ; TP6.1@3100.39,364.17 3094.17,370.4 3094.17,458.34 3251.06,615.24 3251.06,616.22 3264.76,629.92 R11.1@3265.75,629.92 ; R11.1@3267.72,630.91 3315.95,679.13 v2(3316.93,679.13)
ISO_O1: U1.37 U6.4 | length 1694.7
  Bottom Layer w10: U6.4@838.22,629.79 839.32,628.69 901.15,628.69 925.2,604.64 925.2,531.99 954.94,502.25 1427.45,502.25 1909.45,984.25 1948.82,1023.63 1948.82,1155.82 2016.22,1223.23 U1.37@2061.43,1223.23
ISO_O2: U1.36 U6.5 | length 1668.5
  Bottom Layer w10: U6.5@838.22,604.79 860.44,604.79 864.69,600.53 867.48,600.53 905.51,562.5 905.51,561.02 ; 907.32,560.69 907.32,524.59 947.53,484.38 1434.85,484.38 1927.32,976.85 1968.5,1018.04 1968.5,1150.23 2021.81,1203.54 U1.36@2061.43,1203.54
LFXIN: C2.1 U1.43 Y2.2 | length 300.8
  Bottom Layer w10: C2.1@1797.14,1210.66 1797.14,1210.89 1803.95,1217.7 1818.09,1217.7 Y2.2@1840.55,1240.16 ; Y2.2@1871.25,1246.85 1873.75,1249.35 1915.82,1249.35 2007.81,1341.34 U1.43@2061.43,1341.34 2075.87,1341.34 U1.43@2076.77,1342.24
LFXOUT: C3.1 U1.44 Y2.1 | length 286.6
  Bottom Layer w10: C3.1@1797.14,1379.82 1820.96,1379.82 1850.39,1350.38 Y2.1@1850.39,1348.43 ; Y2.1@1871.25,1345.27 1957.65,1345.27 1973.4,1361.02 U1.44@2061.43,1361.02 ; Y2.1@1879.92,1358.27 1899.99,1358.27 Y2.1@1901.68,1359.96
Line: C33.1 D2.4 J18.2
M0: R6.1 U1.4 | length 1166.7
  Top Layer w10: v2(2440.95,1387.8) 2854.33,1801.18 R6.1@3364.17,1801.18
  Bottom Layer w10: v2(2440.95,1387.8) 2444.73,1387.8 2451.82,1380.71 U1.4@2510.25,1380.71
M1: R8.1 U1.55 | length 1220.4
  Bottom Layer w10: U1.55@2256.31,1516.53 2256.31,1602.51 2277.82,1624.02 2720.97,1624.02 2739.95,1605.04 3346.93,1605.04 3365.91,1624.02 v2(3366.14,1624.02)
NetC4_1: C4.1 C5.1 J1.2 R5.2 U1.40 | length 494.5
  Top Layer w15: J1.2@1830.71,846.46 1830.71,925.2 1938.98,1033.46 ; v2(1899.61,1033.46) 1938.98,1033.46 ; v2(1998.03,1092.52) 1938.98,1033.46
  Bottom Layer w10: C4.1@1803.15,1131.89 v2(1860.24,1131.89) ; C5.1@1985.21,1266.7 1994.84,1266.7 1997.82,1269.69 2016.02,1269.69 2027.71,1281.38 2060.52,1281.38 U1.40@2061.43,1282.28
  other v2: 1988.19,1269.69
NetC7_1: C7.1 U1.32 | length 105.4
  Bottom Layer w10: C7.1@2096.46,984.25 C7.1@2096.46,988.19 2096.46,992.13 2103.27,998.94 2111.14,998.94 2138.2,1025.99 U1.32@2138.2,1067.71
NetC9_1: C9.1 R46.2 U1.24 | length 239.1
  Bottom Layer w10: U1.24@2295.68,1067.71 2295.68,929.71 2329.72,895.67 C9.1@2332.68,895.67 ; C9.1@2330.71,885.83 2330.71,838.58 R46.2@2332.68,836.61
NetC10_2: C10.2 C11.1 J3.2 U3.15
NetC12_2: C12.2 C14.1 C17.1 C53.2 J4.2 U2.9 U2.10 U2.11
  other v2: 3858.27,1062.99 3858.27,1092.52 3858.27,1122.05
NetC13_1: C13.1 U3.6 | length 68
  Top Layer w10: C13.1@3690.94,1791.34 3693.38,1791.34 3697.24,1787.48 U3.6@3697.24,1727.36
NetC16_1: C16.1 U2.7 | length 73.1
  Bottom Layer w10: U2.7@3592.52,852.36 C16.1@3592.52,925.43
NetC16_2: C16.2 U2.6 | length 92.5
  Bottom Layer w10: C16.2@3549.21,935.04 3553.15,931.1 3553.15,906.95 3572.83,887.26 U2.6@3572.83,852.36
NetC17_2: C17.2 U2.8 | length 103
  Bottom Layer w10: U2.8@3612.2,852.36 3612.2,866.46 3622.05,876.31 3622.05,912.4 3644.69,935.04 C17.2@3651.57,935.04
NetC18_1: C18.1 U2.37 | length 95.8
  Bottom Layer w10: C18.1@3356.3,759.84 3385.73,759.84 3393.61,767.72 U2.37@3448.82,767.72
NetC26_1: C26.1 C27.1 J9.2 U4.4
NetC28_1: C28.1 J11.2 U5.1
NetC29_1: C29.1 J13.2 R23.2 U6.2
  other v2: 905.51,688.98
NetC30_1: C30.1 J14.2 U7.3 | length 143.6
  Bottom Layer w10: U7.3@690.94,305.12 690.94,375.98 C30.1@698.82,383.86 ; C30.1@702.76,383.86 706.69,383.86 746.06,423.23 v2(748.03,423.23)
  other v2: 748.03,472.44
NetC31_2: C31.2 C32.1 J17.2 U8.2 U8.3
  other v2: 2273.62,2165.35 2322.83,2204.72 2322.83,2244.09
NetC35_1: C35.1 D2.1 S1.1
  other v2: 935.04,1427.17 984.25,1427.17
NetC36_1: C36.1 L2.1 U8.8
NetC36_2: C36.2 U8.7
NetC43_1: C43.1 C44.1 J20.2 U9.3 | length 23.7
  Top Layer w12: 3388.33,2591.23 U9.3@3412.02,2591.23
NetC45_1: C45.1 U9.7 | length 60.4
  Top Layer w10: U9.7@3470.28,2610.91 3505.2,2610.91 3522.24,2627.95 C45.1@3523.62,2627.95
NetC46_1: C46.1 L3.1 U9.5 | length 99.5
  Top Layer w10: L3.1@3543.31,2470.47 L3.1@3555.83,2470.47 ; L3.1@3573.86,2488.51 C46.1@3573.86,2575.48
NetC46_2: C46.2 U9.6 | length 48.7
  Top Layer w10: U9.6@3470.28,2591.23 3501.29,2591.23 C46.2@3513.78,2578.74
NetC47_2: C47.2 U10.7 | length 78.5
  Top Layer w10: U10.7@1664.45,2199.93 1678.78,2199.93 1695.63,2183.08 1716.61,2183.08 C47.2@1730.31,2169.38
NetC48_2: C48.2 U10.6 | length 104
  Top Layer w10: U10.6@1664.45,2180.25 1668.13,2180.25 1668.41,2179.97 1668.41,2167.22 1729.33,2106.3 C48.2@1730.32,2106.3
NetC49_2: C49.2 R38.1 R39.2 U9.8 | length 154.2
  Top Layer w10: U9.8@3472.65,2631.5 R39.2@3472.65,2691.39 ; R39.2@3478.79,2691.39 R38.1@3522.68,2691.39 ; R38.1@3523.62,2696.85 3528.79,2702.02 C49.2@3571.9,2702.02
NetC52_1: C52.1 R24.2 R26.1 U6.16 | length 309.9
  Bottom Layer w10: R24.2@427.23,617.29 R24.2@427.23,623.79 ; 481.38,677.93 481.38,687.09 483.27,688.98 R26.1@492.13,688.98 ; C52.1@501.97,797.24 R26.1@501.97,718.5 515.69,704.79 U6.16@623.65,704.79
  Bottom Layer w15: R24.2@427.23,623.79 481.38,677.93
NetC54_2: C54.2 J23.2 U13.8 | length 75.3
  Bottom Layer w10: U13.8@1190.94,255.91 1190.94,295.28 v2(1210.63,314.96) 1214.42,314.96 C54.2@1217.45,311.93
NetC55_1: C55.1 R25.2 R27.1 U6.11 | length 297.8
  Bottom Layer w10: C55.1@433.07,433.07 R25.2@509.84,433.07 ; R27.1@501.97,501.97 R27.1@509.84,494.09 ; R27.1@501.97,521.65 501.97,532.48 522.56,553.07 548.64,553.07 575.35,579.79 619.16,579.79 U6.11@620.08,580.71
  Bottom Layer w15: R25.2@509.84,433.07 R27.1@509.84,494.09
NetD1_2: D1.2 R1.2 | length 350.5
  Top Layer w10: D1.2@2155.51,1968.5 D1.2@2165.35,1968.5 2312.99,1820.87 v2(2362.2,1820.87)
  Bottom Layer w10: R1.2@2288.99,1798.05 2339.39,1798.05 v2(2362.2,1820.87)
NetD4_2: D4.2 R35.2 | length 81.1
  Top Layer w10: D4.2@1309.06,1988.19 1338.58,2017.72 R35.2@1338.58,2057.09
NetD5_2: D5.2 R40.2 | length 269.1
  Top Layer w10: v2(2519.69,1820.87) D5.2@2519.69,1968.5
  Bottom Layer w10: v2(2519.69,1820.87) 2559.06,1781.5 R40.2@2559.06,1715.75
NetD6_2: D6.2 R43.2 | length 300.5
  Top Layer w10: D6.2@2352.36,1968.5 2440.95,1879.92 v2(2440.95,1820.87)
  Bottom Layer w10: v2(2440.95,1820.87) 2443.62,1818.19 2462.76,1818.19 2528.17,1752.77 R43.2@2528.17,1751.99
NetJ10_2: J10.2 R47.1 | length 225
  Bottom Layer w10: J10.2@1505.91,1850.39 J10.2@1505.91,1862.99
  Bottom Layer w20: J10.2@1505.91,1862.99 1572.05,1929.13 R47.1@1690.94,1929.13
NetL1_1: L1.1 U2.5 | length 131.3
  Bottom Layer w10: 3533.46,964.57 3532.97,964.57 3520.59,952.18 3520.59,914.23 3553.15,881.67 U2.5@3553.15,852.36
NetQ1_1: Q1.1 R2.2 R3.2 | length 83.1
  Bottom Layer w10: R3.2@2057.09,1745.28 2084.46,1745.28 2096.46,1757.27 Q1.1@2096.46,1761.81 ; R3.2@2057.09,1751.97 R2.2@2057.09,1778.35 ; Q1.1@2100.32,1760.65 Q1.1@2108.2,1760.65
NetQ1_3: Q1.3 R1.1 | length 50
  Bottom Layer w10: Q1.3@2214.57,1801.18 2214.57,1800.78 2217.3,1798.05 R1.1@2263,1798.05
NetQ2_1: Q2.1 R41.2 R42.2 | length 99.2
  Bottom Layer w10: Q2.1@2704.72,1730.32 2738.19,1730.32 R41.2@2755.91,1712.6 ; R41.2@2755.91,1702.76 2759.06,1705.91 R42.2@2795.28,1705.91
NetQ2_3: Q2.3 R40.1 | length 44.6
  Bottom Layer w10: R40.1@2559.06,1689.76 2595.62,1689.76 2598.43,1692.57 Q2.3@2598.43,1692.91 ; Q2.3@2625.3,1690.26 Q2.3@2627.95,1692.91
NetQ3_1: Q3.1 R44.2 R45.2 | length 90.8
  Bottom Layer w10: R44.2@2332.68,1742.13 R44.2@2332.68,1738.98 R45.2@2332.68,1705.91 2359.89,1705.91 2372.88,1692.91 Q3.1@2381.89,1692.91
NetQ3_3: Q3.3 R43.1 | length 49.8
  Bottom Layer w10: Q3.3@2480.32,1722.44 2484.47,1726.59 2527.58,1726.59 R43.1@2528.17,1726
NetR3_1: R3.1 U1.49 | length 240.5
  Bottom Layer w10: R3.1@2057.09,1719.29 2057.09,1614.17 2130.2,1541.06 2137.29,1541.06 2138.2,1540.16 U1.49@2138.2,1516.53
NetR4_1: R4.1 U1.42 | length 335.1
  Top Layer w10: R4.1@1889.76,1318.9 1910.43,1318.9 1959.65,1368.11 v2(2116.14,1368.11)
  Bottom Layer w10: U1.42@2061.43,1321.65 2062.33,1322.56 2095.15,1322.56 2116.14,1343.55 v2(2116.14,1368.11)
NetR6_2: R6.2 R7.2 U3.8 | length 305.2
  Top Layer w10: R7.2@3425.2,1732.28 3427.17,1734.25 R6.2@3427.17,1801.18 ; R7.2@3427.17,1732.28 3657.59,1732.28 3657.87,1732.01 U3.8@3657.87,1727.36
NetR8_2: R8.2 R12.2 U3.10 | length 286.9
  Top Layer w10: R12.2@3425.2,1564.96 3427.17,1566.93 R8.2@3427.17,1624.02 ; R8.2@3425.2,1633.86 3437.99,1633.86 3486.21,1682.08 U3.10@3632.28,1682.08
NetR9_2: R9.2 U2.28 | length 216.5
  Bottom Layer w10: R9.2@3543.31,452.76 3546.34,452.76 3553.15,459.57 U2.28@3553.15,663.39
NetR10_2: R10.2 U2.30 | length 106.6
  Bottom Layer w10: R10.2@3484.25,570.87 R10.2@3486.22,570.87 3487.2,570.87 3513.78,597.44 U2.30@3513.78,663.39 U2.30@3513.7,663.31
NetR11_2: R11.2 U2.32 | length 165.4
  Bottom Layer w10: R11.2@3326.77,629.92 R11.2@3328.74,629.92 3440.94,629.92 3467.6,656.57 3474.33,656.57 3474.41,656.65 U2.32@3474.41,663.39
NetR13_2: R13.2 TP7.1 U2.22 | length 642.2
  Bottom Layer w10: U2.22@3671.26,663.39 3671.26,625.73 3676.45,620.54 3676.45,590.82 3675.91,590.28 3675.91,549.48 3723.43,501.97 R13.2@3730.32,501.97 ; R13.2@3730.32,494.09 3736.94,487.47 4137.36,487.47 4152.39,472.44 TP7.1@4173.23,472.44
NetR14_1: R14.1 U2.40 | length 551.7
  Bottom Layer w10: R14.1@2913.39,866.14 R14.1@2915.35,866.14 2916.34,866.14 2955.71,826.77 U2.40@3448.82,826.77
NetR15_1: R15.1 U2.39 | length 550.8
  Bottom Layer w10: R15.1@2942.91,698.82 3001.97,698.82 3110.24,807.09 U2.39@3448.82,807.09
NetR16_1: R16.1 U2.38 | length 813.8
  Bottom Layer w10: R16.1@2807.09,433.07 2854.33,433.07 3070.87,649.61 3070.87,704.47 3153.8,787.4 U2.38@3442.01,787.4
NetR23_1: R23.1 U6.3 | length 215
  Bottom Layer w10: U6.3@838.22,654.79 900.33,654.79 952.8,602.32 952.8,581.65 993.11,541.34 R23.1@994.09,541.34
NetR24_1: R24.1 U6.15 | length 123.9
  Bottom Layer w10: R24.1@507.23,617.29 507.23,623.79 563.23,679.79 600.33,679.79 600.39,679.72 600.39,678.75 U6.15@600.33,678.69
NetR25_1: R25.1 U6.10 | length 137.4
  Bottom Layer w10: R25.1@572.83,433.07 572.83,531.48 U6.10@600.39,559.04
NetR28_2: R28.2 U8.4 | length 105.8
  Top Layer w10: U8.4@2347.88,2137.68 2355.87,2145.67 U8.4@2372.05,2145.67 ; U8.4@2386.19,2142.52 2386.89,2142.52 2391.73,2137.68 R28.2@2391.73,2066.93
NetR29_1: R29.1 R30.2 U8.5 | length 155.3
  Top Layer w10: R30.2@2693.7,2142.52 R30.2@2695.26,2144.08 ; R30.2@2700.37,2138.96 R30.2@2707.08,2145.67
  Top Layer w20: U8.5@2612.56,2142.52 R30.2@2693.7,2142.52 ; R30.2@2700.37,2138.96 R29.1@2762.87,2138.96
NetR31_1: R31.1 R32.2 U10.3 | length 183.3
  Top Layer w10: v3(1525.59,2224.41) 1525.97,2224.03 1535.91,2224.03 1540.32,2219.62 U10.3@1554.22,2219.62
  Bottom Layer w10: R31.1@1472.44,2151.57 1476.38,2155.51 R31.1@1479.33,2155.51 ; R31.1@1478.35,2155.51 R31.1@1479.33,2155.51 ; v3(1525.59,2224.41) 1525.59,2204.72 1493.03,2172.17 1493.03,2169.21 R31.1@1479.33,2155.51
  Bottom Layer w25: R32.2@1472.44,2096.46 R31.1@1472.44,2151.57
NetR33_2: R33.2 R34.2 U10.5 | length 261.3
  Top Layer w10: U10.5@1554.22,2180.25 1522.73,2180.25 1515.75,2173.27 1515.75,2132.84 1561.59,2087 1564.58,2087 v3(1564.96,2086.61)
  Bottom Layer w10: R33.2@1496.06,2037.4 R34.2@1553.15,2037.4 1564.96,2049.21 v3(1564.96,2086.61)
NetR35_1: R35.1 U10.4 | length 237.8
  Top Layer w10: R35.1@1338.58,2146.3 1456.83,2146.3 1510.46,2199.93 U10.4@1554.22,2199.93
NetR36_1: R36.1 U10.8 | length 70.8
  Top Layer w10: U10.8@1664.45,2219.62 1718.35,2219.62 R36.1@1730.31,2231.58
NetR37_1: R37.1 U10.9 | length 105.5
  Top Layer w10: U10.9@1664.73,2239.58 U10.9@1664.45,2239.3 1687.06,2239.3 1692.91,2245.16 1692.91,2287.45 1698.77,2293.31 R37.1@1722.44,2293.31
NetR42_1: R42.1 U1.63 | length 673.6
  Top Layer w10: v2(2440.95,1466.54) 2753.23,1778.82 2753.23,1788.66 v2(2755.91,1791.34)
  Bottom Layer w10: U1.63@2413.79,1516.53 2414.69,1515.63 2414.69,1482.81 2428.3,1469.21 2438.27,1469.21 v2(2440.95,1466.54) ; v2(2755.91,1791.34) 2816.42,1730.83 2816.42,1691.52 2808.88,1683.98 2798.54,1683.98 2795.28,1680.71 R42.1@2795.28,1679.92
NetR45_1: R45.1 U1.62 | length 335.8
  Top Layer w10: v2(2332.68,1673.23) 2411.42,1594.49 v2(2411.42,1446.85)
  Bottom Layer w10: U1.62@2394.1,1516.53 2394.1,1467.95 2411.42,1450.64 v2(2411.42,1446.85)
NetR48_1: R48.1 R49.2 U13.3 | length 102.3
  Top Layer w10: R48.1@1305.12,206.69 1305.12,244.09 1318.9,257.87 R49.2@1318.9,261.81 R49.2@1318.9,265.75
  Bottom Layer w10: U13.3@1265.75,216.54 1286.89,216.54 1296.73,206.69 v2(1299.21,206.69)
NetR50_1: R50.1 U13.5 | length 376.3
  Top Layer w10: R50.1@964.57,305.12 989.41,305.12 1000.39,316.09 1000.39,318.83 1028.02,346.46 1120.08,346.46 1151.57,314.96 v2(1151.57,196.85)
  Bottom Layer w10: v2(1151.57,196.85) U13.5@1190.94,196.85
NetR50_2: R50.2 R51.2 R52.2 | length 138.6
  Top Layer w10: R52.2@937.01,246.06 R52.2@944.88,246.06
  Top Layer w15: R50.2@911.42,305.12 911.42,271.65 R52.2@937.01,246.06 ; R50.2@915.35,303.15 R51.2@915.35,364.17
NetR53_1: R53.1 TP11.1 U1.11 | length 331.7
  Bottom Layer w10: U1.11@2510.25,1242.91 2635.04,1242.91 2726.38,1151.57 TP11.1@2736.22,1151.57 ; TP11.1@2746.06,1131.89 R53.1@2794.08,1083.87
Neutral: C34.1 D2.3 J18.1
  other v2: 433.07,1181.1 482.28,1181.1
nSCS: U1.29 U2.36 | length 1569.7
  Top Layer w10: v2@2645.08,846.46 2972.44,846.46 v2(3110.24,708.66)
  Bottom Layer w10: U1.29@2197.25,1067.71 2197.25,1134.26 2214.57,1151.57 2342.52,1151.57 2383.98,1110.12 2443.57,1110.12 2485.5,1068.18 2485.5,1008.59 v2@2652.69,841.41 ; v2(3110.24,708.66) 3129.92,728.35 3379.52,728.35 3399.2,748.03 U2.36@3448.82,748.03
  other v2: 2647.64,846.46
nSLEEP: U1.28 U3.14 | length 2013.1
  Top Layer w10: v2(2263.78,1122.05) 2263.78,988.44 2332.22,920.01 2425.91,920.01 2710.95,1205.04 3232.6,1205.04 3277.56,1250 3277.56,1338.58 3377.8,1438.82 3513.15,1438.82 3677.55,1603.23 U3.14@3677.55,1617.12
  Bottom Layer w10: U1.28@2216.94,1067.71 2217.84,1068.62 2217.84,1101.43 2236.78,1120.37 2262.1,1120.37 v2(2263.78,1122.05)
nSLP: U1.2 U2.23 | length 1740.4
  Top Layer w10: v2@2992.13,1041.37 2992.13,965.97 3285.42,672.67 3347.86,610.24 v2(3651.57,610.24)
  Bottom Layer w10: U1.2@2510.25,1420.08 2890.95,1420.08 2992.13,1318.9 v2@2992.13,1037.65 ; v2(3651.57,610.24) U2.23@3651.57,663.39
  other v2: 2992.13,1043.31
OUTA: J7.3 U2.13 U2.14
OUTB: J7.2 U2.16 U2.17
OUTC: J7.1 U2.19 U2.20
PGND: C12.1 C14.2 C53.1 TP10.1 U2.12 U2.15 U2.18
  other v1: 3720.47,728.35 3720.47,787.4 3690.94,856.3 3848.2,877.44 3877.73,877.44 3848.2,897.12 3877.73,897.12 3769.69,915.35 3789.37,915.35 3848.2,916.81 3877.73,916.81 3789.37,974.41 3789.37,994.09 3789.37,1053.15 3789.37,1072.83
RESET: C8.1 J2.10 R5.1 U1.38 | length 917.4
  Top Layer w10: J2.10@1528.63,598.32 J2.10@1528.35,598.03 1568.7,598.03 1742.13,771.46 v2(1742.13,856.3)
  Bottom Layer w10: v2@1743.12,856.3 1840.28,953.46 1840.28,974.14 C8.1@1840.55,974.41 ; C8.1@1844.49,974.41 1844.49,1033.46 1844.49,1076.77 2010.63,1242.91 U1.38@2061.43,1242.91
RXD: U1.31 U7.4 | length 1855
  Bottom Layer w10: U7.4@716.54,305.12 716.54,348.45 820.85,452.76 1043.31,452.76 ; 1047.22,452.76 1445.38,452.76 1809.55,816.93 2037.4,816.93 2135.83,915.35 2135.83,951.62 2157.88,973.67 U1.31@2157.88,1067.71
